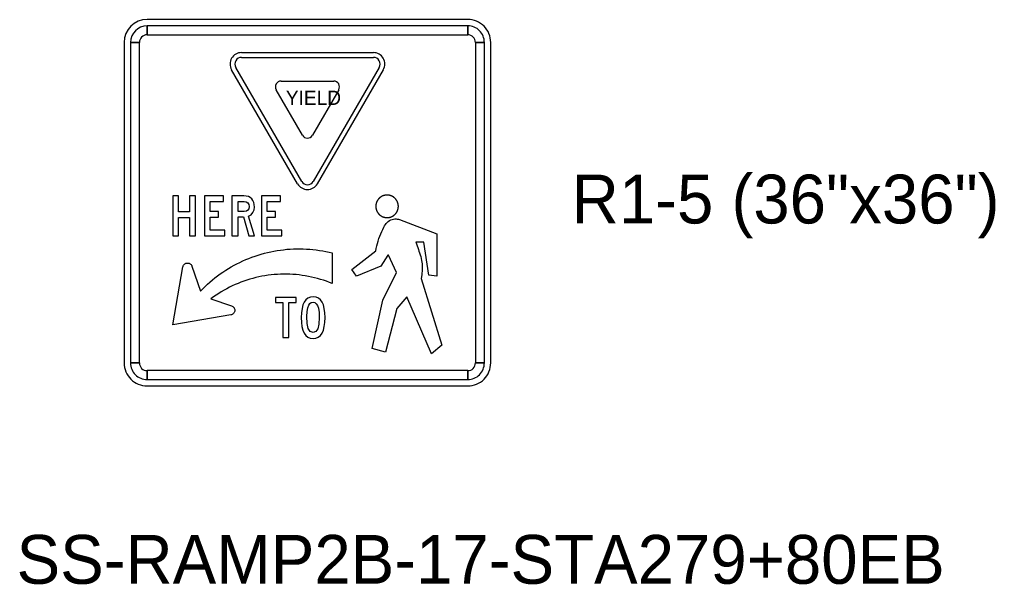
# Model space of a CAD drawing. Extents: x 620856.8 to 620948.6, y 415598.8 to 415658.2.
# Drawn here: x 620886.92 to 620894.91, y 415617.41 to 415622.04 of the extents above; entities that cross this region are included whole.
import ezdxf

# ---------------------------------------------------------------- set-up
doc = ezdxf.new("R2010")
doc.units = 0
doc.layers.add('SIGNS', color=7, linetype='Continuous')

msp = doc.modelspace()

# ---------------------------------------------------------------- linework, layer by layer
at = {"layer": 'SIGNS'}
for p, q in [((620890.5903, 415622.0407), (620887.9653, 415622.0407)), ((620890.5903, 415622.0407), (620887.9653, 415622.0407)), ((620887.9653, 415621.9157), (620887.9653, 415621.9886)), ((620890.5903, 415621.9886), (620890.5903, 415621.9157)), ((620887.7778, 415621.8532), (620887.7778, 415619.2282)), ((620887.7778, 415621.8532), (620887.7778, 415619.2282)), ((620887.8298, 415621.8532), (620887.9028, 415621.8532)), ((620890.6528, 415621.8532), (620890.7257, 415621.8532)), ((620890.7778, 415619.2282), (620890.7778, 415621.8532)), ((620890.7778, 415619.2282), (620890.7778, 415621.8532)), ((620888.7384, 415621.7698), (620889.8171, 415621.7698)), ((620888.7384, 415621.7309), (620889.8171, 415621.7309)), ((620889.1968, 415620.6954), (620888.6575, 415621.6296)), ((620889.2305, 415620.7149), (620888.6912, 415621.649)), ((620889.8643, 415621.649), (620889.325, 415620.7149)), ((620889.8981, 415621.6296), (620889.3587, 415620.6954)), ((620889.0623, 415621.5361), (620889.4932, 415621.5361)), ((620889.2373, 415621.0928), (620889.0219, 415621.4659)), ((620889.5337, 415621.4659), (620889.3182, 415621.0928)), ((620889.931, 415620.3798), (620889.9397, 415620.3879)), ((620889.9397, 415620.3879), (620889.9493, 415620.3946)), ((620889.9493, 415620.3946), (620889.9592, 415620.4002)), ((620889.9592, 415620.4002), (620889.9699, 415620.4044)), ((620889.9699, 415620.4044), (620889.9811, 415620.4069)), ((620889.9811, 415620.4069), (620889.9928, 415620.4079)), ((620889.9928, 415620.4079), (620890.0032, 415620.4078)), ((620890.0032, 415620.4078), (620890.0132, 415620.4069)), ((620890.0132, 415620.4069), (620890.0229, 415620.405)), ((620890.0229, 415620.405), (620890.0323, 415620.4021)), ((620890.0323, 415620.4021), (620890.3379, 415620.2852)), ((620889.8855, 415620.3038), (620889.8939, 415620.3225)), ((620889.8939, 415620.3225), (620889.9026, 415620.3411)), ((620889.9026, 415620.3411), (620889.9086, 415620.3514)), ((620889.9086, 415620.3514), (620889.9154, 415620.3615)), ((620889.9154, 415620.3615), (620889.9229, 415620.3709)), ((620889.9229, 415620.3709), (620889.931, 415620.3798)), ((620889.8508, 415620.2071), (620889.8566, 415620.227)), ((620889.8566, 415620.227), (620889.8631, 415620.2465)), ((620889.8631, 415620.2465), (620889.8701, 415620.2659)), ((620889.8701, 415620.2659), (620889.8776, 415620.2849)), ((620889.8776, 415620.2849), (620889.8855, 415620.3038)), ((620890.3379, 415620.2852), (620890.3379, 415619.9401)), ((620889.6403, 415619.9951), (620889.8381, 415620.1458)), ((620889.8381, 415620.1458), (620889.8415, 415620.1665)), ((620889.8415, 415620.1665), (620889.8458, 415620.187)), ((620889.8458, 415620.187), (620889.8508, 415620.2071)), ((620890.229, 415620.2187), (620890.1657, 415620.2182)), ((620890.1657, 415620.2182), (620890.1705, 415620.2033)), ((620890.1705, 415620.2033), (620890.1754, 415620.1885)), ((620890.1754, 415620.1885), (620890.1804, 415620.1737)), ((620890.1804, 415620.1737), (620890.1855, 415620.1588)), ((620890.1855, 415620.1588), (620890.1904, 415620.144)), ((620890.2714, 415619.9479), (620890.229, 415620.2187)), ((620889.4548, 415620.1357), (620889.4811, 415620.1296)), ((620889.4811, 415620.1296), (620889.4811, 415619.8785)), ((620889.9366, 415620.1118), (620889.8796, 415620.0214)), ((620889.9374, 415620.1119), (620889.9366, 415620.1118)), ((620889.9382, 415620.1119), (620889.9374, 415620.1119)), ((620889.9387, 415620.1118), (620889.9382, 415620.1119)), ((620889.9395, 415620.1116), (620889.9387, 415620.1118)), ((620889.94, 415620.1113), (620889.9395, 415620.1116)), ((620890.0057, 415619.9704), (620889.94, 415620.1113)), ((620890.1904, 415620.144), (620890.1953, 415620.1293)), ((620890.1953, 415620.1293), (620890.2, 415620.1143)), ((620890.2, 415620.1143), (620890.2045, 415620.0993)), ((620890.2045, 415620.0993), (620890.2085, 415620.084)), ((620890.2085, 415620.084), (620890.2124, 415620.0687)), ((620890.2124, 415620.0687), (620890.2146, 415620.0541)), ((620888.1769, 415619.5407), (620888.2583, 415620.0147)), ((620888.3329, 415620.0208), (620888.4029, 415619.8176)), ((620889.6802, 415619.9401), (620889.6403, 415619.9951)), ((620889.8796, 415620.0214), (620889.6802, 415619.9401)), ((620890.2146, 415620.0541), (620890.2162, 415620.0392)), ((620890.2169, 415619.9944), (620890.216, 415619.9794)), ((620890.2162, 415620.0392), (620890.217, 415620.0242)), ((620890.2173, 415620.0094), (620890.2169, 415619.9944)), ((620890.217, 415620.0242), (620890.2173, 415620.0094)), ((620889.8948, 415619.742), (620890.0063, 415619.9698)), ((620890.0063, 415619.9698), (620890.0057, 415619.9704)), ((620890.213, 415619.9494), (620890.2085, 415619.9199)), ((620890.2085, 415619.9199), (620890.3786, 415619.3738)), ((620890.2147, 415619.9644), (620890.213, 415619.9494)), ((620890.216, 415619.9794), (620890.2147, 415619.9644)), ((620890.3379, 415619.9401), (620890.2714, 415619.9479)), ((620889.4811, 415619.8785), (620889.4571, 415619.888)), ((620888.4881, 415619.7545), (620888.657, 415619.6966)), ((620890.0909, 415619.7696), (620890.0101, 415619.6756)), ((620890.2936, 415619.3023), (620890.0909, 415619.7696)), ((620889.8074, 415619.3468), (620889.8948, 415619.742)), ((620890.0101, 415619.6756), (620889.916, 415619.3178)), ((620888.651, 415619.6221), (620888.1769, 415619.5407)), ((620889.916, 415619.3178), (620889.8074, 415619.3468)), ((620890.3786, 415619.3738), (620890.2936, 415619.3023)), ((620887.9028, 415619.2282), (620887.8298, 415619.2282)), ((620890.7257, 415619.2282), (620890.6528, 415619.2282)), ((620887.9653, 415619.0927), (620887.9653, 415619.1657)), ((620890.5903, 415619.1657), (620890.5903, 415619.0927)), ((620887.9653, 415619.0407), (620890.5903, 415619.0407)), ((620887.9653, 415619.0407), (620890.5903, 415619.0407))]:
    msp.add_line(p, q, dxfattribs=at)
for points in [[(620890.5903, 415621.9886), (620887.9653, 415621.9886), (620887.9653, 415621.9157), (620890.5903, 415621.9157), (620890.5903, 415621.9886), (620890.5903, 415621.9886)], [(620887.8298, 415621.8532), (620887.8298, 415619.2282), (620887.9028, 415619.2282), (620887.9028, 415621.8532), (620887.8298, 415621.8532), (620887.8298, 415621.8532)], [(620890.7257, 415619.2282), (620890.7257, 415621.8532), (620890.6528, 415621.8532), (620890.6528, 415619.2282), (620890.7257, 415619.2282), (620890.7257, 415619.2282)], [(620888.1769, 415620.2698), (620888.2218, 415620.2698), (620888.2218, 415620.4199), (620888.3115, 415620.4199), (620888.3115, 415620.2698), (620888.3615, 415620.2698), (620888.3615, 415620.5967), (620888.3115, 415620.5967), (620888.3115, 415620.4656), (620888.2218, 415620.4656), (620888.2218, 415620.5967), (620888.1769, 415620.5967)], [(620888.6027, 415620.3147), (620888.4823, 415620.3147), (620888.4823, 415620.4236), (620888.5506, 415620.4236), (620888.5506, 415620.4685), (620888.4823, 415620.4685), (620888.4823, 415620.5518), (620888.5902, 415620.5518), (620888.5902, 415620.5967), (620888.4346, 415620.5967), (620888.4346, 415620.2698), (620888.6027, 415620.2698)], [(620889.0691, 415620.3147), (620888.9487, 415620.3147), (620888.9487, 415620.4236), (620889.017, 415620.4236), (620889.017, 415620.4685), (620888.9487, 415620.4685), (620888.9487, 415620.5518), (620889.0566, 415620.5518), (620889.0566, 415620.5967), (620888.9009, 415620.5967), (620888.9009, 415620.2698), (620889.0691, 415620.2698)], [(620889.077, 415619.4365), (620889.1245, 415619.4365), (620889.1245, 415619.7223), (620889.1855, 415619.7223), (620889.1855, 415619.7634), (620889.0173, 415619.7634), (620889.0173, 415619.7223), (620889.077, 415619.7223)], [(620887.9653, 415619.0927), (620890.5903, 415619.0927), (620890.5903, 415619.1657), (620887.9653, 415619.1657), (620887.9653, 415619.0927), (620887.9653, 415619.0927)]]:
    msp.add_lwpolyline(points, close=True, dxfattribs=at)
for points in [[(620888.6594, 415620.2698), (620888.7107, 415620.2698), (620888.7107, 415620.4255), (620888.7543, 415620.4255), (620888.7971, 415620.2698), (620888.844, 415620.2698), (620888.7965, 415620.431), (620888.8168, 415620.4424), (620888.8322, 415620.4604), (620888.841, 415620.4813), (620888.844, 415620.5052), (620888.8426, 415620.5248), (620888.8384, 415620.5424), (620888.8315, 415620.5579), (620888.8219, 415620.5712), (620888.8092, 415620.5823), (620888.7941, 415620.5903), (620888.7768, 415620.5951), (620888.7572, 415620.5967), (620888.6594, 415620.5967), (620888.6594, 415620.2698)], [(620888.7107, 415620.4685), (620888.7107, 415620.5518), (620888.7587, 415620.5518), (620888.7755, 415620.549), (620888.7889, 415620.5405), (620888.7975, 415620.5272), (620888.8004, 415620.51), (620888.7978, 415620.4917), (620888.7903, 415620.4789), (620888.7778, 415620.471), (620888.7602, 415620.4685), (620888.7107, 415620.4685)], [(620889.913, 415620.6017), (620889.9114, 415620.6014), (620889.9098, 415620.601), (620889.9082, 415620.6007), (620889.9066, 415620.6003), (620889.9051, 415620.5999), (620889.9035, 415620.5995), (620889.902, 415620.599), (620889.9004, 415620.5985), (620889.8989, 415620.598), (620889.8974, 415620.5974), (620889.8959, 415620.5969), (620889.8944, 415620.5963), (620889.8929, 415620.5956), (620889.8914, 415620.595), (620889.8899, 415620.5943), (620889.8885, 415620.5936), (620889.8871, 415620.5929), (620889.8856, 415620.5921), (620889.8842, 415620.5913), (620889.8828, 415620.5905), (620889.8814, 415620.5897), (620889.88, 415620.5888), (620889.8787, 415620.588), (620889.8774, 415620.5871), (620889.876, 415620.5861), (620889.8747, 415620.5852), (620889.8734, 415620.5842), (620889.8721, 415620.5832), (620889.8709, 415620.5822), (620889.8697, 415620.5812), (620889.8684, 415620.5801), (620889.8672, 415620.5791), (620889.866, 415620.578), (620889.8649, 415620.5768), (620889.8637, 415620.5757), (620889.8626, 415620.5745), (620889.8615, 415620.5734), (620889.8604, 415620.5722), (620889.8594, 415620.5709), (620889.8583, 415620.5697), (620889.8573, 415620.5685), (620889.8563, 415620.5672), (620889.8553, 415620.5659), (620889.8544, 415620.5646), (620889.8534, 415620.5633), (620889.8525, 415620.5619), (620889.8517, 415620.5606), (620889.8508, 415620.5592), (620889.85, 415620.5578), (620889.8492, 415620.5564), (620889.8484, 415620.555), (620889.8476, 415620.5536), (620889.8469, 415620.5522), (620889.8462, 415620.5507), (620889.8455, 415620.5492), (620889.8448, 415620.5478), (620889.8442, 415620.5463), (620889.8436, 415620.5448), (620889.843, 415620.5433), (620889.8425, 415620.5418), (620889.8419, 415620.5402), (620889.8414, 415620.5387), (620889.841, 415620.5372), (620889.8405, 415620.5356), (620889.8401, 415620.534), (620889.8397, 415620.5325), (620889.8393, 415620.5309), (620889.839, 415620.5293), (620889.8387, 415620.5277), (620889.8384, 415620.5261), (620889.8381, 415620.5246), (620889.8379, 415620.523), (620889.8377, 415620.5213), (620889.8376, 415620.5197), (620889.8374, 415620.5181), (620889.8373, 415620.5165), (620889.8372, 415620.5149), (620889.8372, 415620.5133), (620889.8371, 415620.5117), (620889.8371, 415620.5101), (620889.8372, 415620.5084), (620889.8372, 415620.5068), (620889.8373, 415620.5052), (620889.8374, 415620.5036), (620889.8376, 415620.502), (620889.8377, 415620.5004), (620889.8379, 415620.4988), (620889.8381, 415620.4972), (620889.8384, 415620.4956), (620889.8387, 415620.494), (620889.839, 415620.4924), (620889.8393, 415620.4908), (620889.8397, 415620.4893), (620889.8401, 415620.4877), (620889.8405, 415620.4861), (620889.841, 415620.4846), (620889.8414, 415620.483), (620889.8419, 415620.4815), (620889.8425, 415620.48), (620889.843, 415620.4785)], [(620890.0217, 415620.5109), (620890.0217, 415620.5125), (620890.0217, 415620.5141), (620890.0216, 415620.5157), (620890.0215, 415620.5173), (620890.0214, 415620.5189), (620890.0212, 415620.5205), (620890.021, 415620.5221), (620890.0208, 415620.5238), (620890.0206, 415620.5253), (620890.0203, 415620.5269), (620890.02, 415620.5285), (620890.0197, 415620.5301), (620890.0193, 415620.5317), (620890.019, 415620.5333), (620890.0185, 415620.5348), (620890.0181, 415620.5364), (620890.0177, 415620.5379), (620890.0172, 415620.5395), (620890.0167, 415620.541), (620890.0161, 415620.5425), (620890.0155, 415620.544), (620890.015, 415620.5455), (620890.0143, 415620.547), (620890.0137, 415620.5485), (620890.013, 415620.55), (620890.0123, 415620.5514), (620890.0116, 415620.5529), (620890.0108, 415620.5543), (620890.0101, 415620.5557), (620890.0093, 415620.5571), (620890.0085, 415620.5585), (620890.0076, 415620.5599), (620890.0067, 415620.5613), (620890.0058, 415620.5626), (620890.0049, 415620.5639), (620890.004, 415620.5652), (620890.003, 415620.5665), (620890.002, 415620.5678), (620890.001, 415620.5691), (620890, 415620.5703), (620889.999, 415620.5716), (620889.9979, 415620.5728), (620889.9968, 415620.574), (620889.9957, 415620.5751), (620889.9945, 415620.5763), (620889.9934, 415620.5774), (620889.9922, 415620.5785), (620889.991, 415620.5796), (620889.9898, 415620.5807), (620889.9886, 415620.5817), (620889.9873, 415620.5827), (620889.9861, 415620.5837), (620889.9848, 415620.5847), (620889.9835, 415620.5857), (620889.9822, 415620.5866), (620889.9808, 415620.5875), (620889.9795, 415620.5884), (620889.9781, 415620.5893), (620889.9767, 415620.5901), (620889.9753, 415620.5909), (620889.9739, 415620.5917), (620889.9725, 415620.5925), (620889.9711, 415620.5932), (620889.9696, 415620.5939), (620889.9682, 415620.5946), (620889.9667, 415620.5953), (620889.9652, 415620.5959), (620889.9637, 415620.5966), (620889.9622, 415620.5971), (620889.9607, 415620.5977), (620889.9592, 415620.5982), (620889.9576, 415620.5987), (620889.9561, 415620.5992), (620889.9545, 415620.5997), (620889.953, 415620.6001), (620889.9514, 415620.6005), (620889.9498, 415620.6009), (620889.9483, 415620.6012), (620889.9467, 415620.6015), (620889.9451, 415620.6018), (620889.9435, 415620.6021), (620889.9419, 415620.6023), (620889.9403, 415620.6025), (620889.9387, 415620.6027), (620889.9371, 415620.6028), (620889.9355, 415620.603), (620889.9339, 415620.6031), (620889.9322, 415620.6031), (620889.9306, 415620.6032), (620889.929, 415620.6032), (620889.9274, 415620.6031), (620889.9258, 415620.6031), (620889.9242, 415620.603), (620889.9226, 415620.6029), (620889.921, 415620.6028), (620889.9193, 415620.6026), (620889.9177, 415620.6024), (620889.9161, 415620.6022), (620889.9145, 415620.602), (620889.913, 415620.6017)], [(620889.843, 415620.4785), (620889.8436, 415620.477), (620889.8442, 415620.4755), (620889.8448, 415620.474), (620889.8455, 415620.4725), (620889.8462, 415620.471), (620889.8469, 415620.4696), (620889.8476, 415620.4681), (620889.8484, 415620.4667), (620889.8492, 415620.4653), (620889.85, 415620.4639), (620889.8508, 415620.4625), (620889.8517, 415620.4612), (620889.8525, 415620.4598), (620889.8534, 415620.4585), (620889.8544, 415620.4571), (620889.8553, 415620.4558), (620889.8563, 415620.4546), (620889.8573, 415620.4533), (620889.8583, 415620.452), (620889.8594, 415620.4508), (620889.8604, 415620.4496), (620889.8615, 415620.4484), (620889.8626, 415620.4472), (620889.8637, 415620.446), (620889.8649, 415620.4449), (620889.866, 415620.4438), (620889.8672, 415620.4427), (620889.8684, 415620.4416), (620889.8697, 415620.4405), (620889.8709, 415620.4395), (620889.8721, 415620.4385), (620889.8734, 415620.4375), (620889.8747, 415620.4365), (620889.876, 415620.4356), (620889.8774, 415620.4347), (620889.8787, 415620.4338), (620889.88, 415620.4329), (620889.8814, 415620.432), (620889.8828, 415620.4312), (620889.8842, 415620.4304), (620889.8856, 415620.4296), (620889.8871, 415620.4289), (620889.8885, 415620.4281), (620889.8899, 415620.4274), (620889.8914, 415620.4268), (620889.8929, 415620.4261), (620889.8944, 415620.4255), (620889.8959, 415620.4249), (620889.8974, 415620.4243), (620889.8989, 415620.4238), (620889.9004, 415620.4232), (620889.902, 415620.4228), (620889.9035, 415620.4223), (620889.9051, 415620.4218), (620889.9066, 415620.4214), (620889.9082, 415620.421), (620889.9098, 415620.4207), (620889.9114, 415620.4204), (620889.913, 415620.4201), (620889.9145, 415620.4198), (620889.9161, 415620.4195), (620889.9177, 415620.4193), (620889.9193, 415620.4191), (620889.921, 415620.419), (620889.9226, 415620.4188), (620889.9242, 415620.4187), (620889.9258, 415620.4187), (620889.9274, 415620.4186), (620889.929, 415620.4186), (620889.9306, 415620.4186), (620889.9322, 415620.4186), (620889.9339, 415620.4187), (620889.9355, 415620.4188), (620889.9371, 415620.4189), (620889.9387, 415620.419), (620889.9403, 415620.4192), (620889.9419, 415620.4194), (620889.9435, 415620.4197), (620889.9451, 415620.4199), (620889.9467, 415620.4202), (620889.9483, 415620.4205), (620889.9498, 415620.4209), (620889.9514, 415620.4212), (620889.953, 415620.4216), (620889.9545, 415620.4221), (620889.9561, 415620.4225), (620889.9576, 415620.423), (620889.9592, 415620.4235), (620889.9607, 415620.424), (620889.9622, 415620.4246), (620889.9637, 415620.4252), (620889.9652, 415620.4258), (620889.9667, 415620.4264), (620889.9682, 415620.4271), (620889.9696, 415620.4278), (620889.9711, 415620.4285), (620889.9725, 415620.4293), (620889.9739, 415620.43), (620889.9753, 415620.4308), (620889.9767, 415620.4316)], [(620889.9767, 415620.4316), (620889.9781, 415620.4325), (620889.9795, 415620.4333), (620889.9808, 415620.4342), (620889.9822, 415620.4351), (620889.9835, 415620.4361), (620889.9848, 415620.437), (620889.9861, 415620.438), (620889.9873, 415620.439), (620889.9886, 415620.44), (620889.9898, 415620.4411), (620889.991, 415620.4421), (620889.9922, 415620.4432), (620889.9934, 415620.4443), (620889.9945, 415620.4455), (620889.9957, 415620.4466), (620889.9968, 415620.4478), (620889.9979, 415620.449), (620889.999, 415620.4502), (620890, 415620.4514), (620890.001, 415620.4527), (620890.002, 415620.4539), (620890.003, 415620.4552), (620890.004, 415620.4565), (620890.0049, 415620.4578), (620890.0058, 415620.4591), (620890.0067, 415620.4605), (620890.0076, 415620.4618), (620890.0085, 415620.4632), (620890.0093, 415620.4646), (620890.0101, 415620.466), (620890.0108, 415620.4674), (620890.0116, 415620.4689), (620890.0123, 415620.4703), (620890.013, 415620.4718), (620890.0137, 415620.4732), (620890.0143, 415620.4747), (620890.015, 415620.4762), (620890.0155, 415620.4777), (620890.0161, 415620.4792), (620890.0167, 415620.4807), (620890.0172, 415620.4823), (620890.0177, 415620.4838), (620890.0181, 415620.4854), (620890.0185, 415620.4869), (620890.019, 415620.4885), (620890.0193, 415620.4901), (620890.0197, 415620.4916), (620890.02, 415620.4932), (620890.0203, 415620.4948), (620890.0206, 415620.4964), (620890.0208, 415620.498), (620890.021, 415620.4996), (620890.0212, 415620.5012), (620890.0214, 415620.5028), (620890.0215, 415620.5044), (620890.0216, 415620.506), (620890.0217, 415620.5076), (620890.0217, 415620.5093), (620890.0217, 415620.5109), (620890.0217, 415620.5109), (620890.0217, 415620.5109)], [(620888.4029, 415619.8176), (620888.4216, 415619.8367), (620888.4406, 415619.8553), (620888.46, 415619.8736), (620888.4801, 415619.8914), (620888.5007, 415619.9086), (620888.5212, 415619.9253), (620888.5425, 415619.9417), (620888.5642, 415619.9573), (620888.5863, 415619.9725), (620888.6087, 415619.9873), (620888.6312, 415620.0014), (620888.6544, 415620.0151), (620888.6776, 415620.028), (620888.7012, 415620.0406), (620888.7251, 415620.0524), (620888.7495, 415620.0638), (620888.7738, 415620.0744), (620888.7986, 415620.0847), (620888.8237, 415620.0942), (620888.8488, 415620.1033), (620888.8743, 415620.1117), (620888.8998, 415620.1193), (620888.9256, 415620.1266), (620888.9515, 415620.133), (620888.9774, 415620.1387), (620889.0036, 415620.1441), (620889.0299, 415620.1486), (620889.0565, 415620.1528), (620889.0831, 415620.1559), (620889.1098, 415620.1589), (620889.1364, 415620.1608), (620889.163, 415620.1623), (620889.1897, 415620.1631), (620889.2163, 415620.1631), (620889.2433, 415620.1627), (620889.2699, 415620.1616), (620889.2966, 415620.1597), (620889.3232, 415620.1574), (620889.3498, 415620.1543), (620889.3761, 415620.1505), (620889.4027, 415620.1463), (620889.429, 415620.1414), (620889.4548, 415620.1357)], [(620888.2583, 415620.0147), (620888.2595, 415620.0196), (620888.2614, 415620.0242), (620888.2641, 415620.0288), (620888.2667, 415620.033), (620888.2705, 415620.0368), (620888.2743, 415620.0398), (620888.2789, 415620.0425), (620888.2835, 415620.0444), (620888.2884, 415620.0459), (620888.2933, 415620.0467), (620888.2983, 415620.0467), (620888.3036, 415620.0463), (620888.3086, 415620.0448), (620888.3131, 415620.0429), (620888.3177, 415620.0406), (620888.3215, 415620.0375), (620888.3253, 415620.0337), (620888.3283, 415620.0299), (620888.331, 415620.0254), (620888.3329, 415620.0208)], [(620889.4571, 415619.888), (620889.4332, 415619.8971), (620889.4092, 415619.9051), (620889.3848, 415619.9127), (620889.3601, 415619.92), (620889.3358, 415619.9264), (620889.3106, 415619.9321), (620889.2855, 415619.9375), (620889.2604, 415619.9417), (620889.2353, 415619.9458), (620889.2102, 415619.9489), (620889.1847, 415619.9515), (620889.1592, 415619.9535), (620889.1337, 415619.955), (620889.1083, 415619.9557), (620889.0828, 415619.9557), (620889.0573, 415619.955), (620889.0318, 415619.9538), (620889.0063, 415619.9519), (620888.9808, 415619.9493), (620888.9553, 415619.9462), (620888.9302, 415619.9424), (620888.9051, 415619.9379), (620888.88, 415619.9329), (620888.8553, 415619.9272), (620888.8305, 415619.9207), (620888.8058, 415619.9139), (620888.7814, 415619.9063), (620888.7575, 415619.8983), (620888.7335, 415619.8895), (620888.7095, 415619.88), (620888.6863, 415619.8701), (620888.6628, 415619.8595), (620888.6399, 415619.8484), (620888.6171, 415619.8367), (620888.595, 415619.8245), (620888.573, 415619.8115), (620888.5513, 415619.7982), (620888.5296, 415619.7842), (620888.5087, 415619.7697), (620888.4881, 415619.7545)], [(620889.4218, 415619.6004), (620889.4202, 415619.64), (620889.4157, 415619.6745), (620889.4082, 415619.7035), (620889.3977, 415619.7274), (620889.384, 415619.7459), (620889.3674, 415619.7592), (620889.3478, 415619.7671), (620889.3253, 415619.7698), (620889.3023, 415619.7671), (620889.2823, 415619.7592), (620889.2655, 415619.7459), (620889.2518, 415619.7274), (620889.2411, 415619.7035), (620889.2334, 415619.6745), (620889.2288, 415619.64), (620889.2273, 415619.6004), (620889.2287, 415619.5604), (620889.2332, 415619.5258), (620889.2407, 415619.4965), (620889.2513, 415619.4726), (620889.2647, 415619.4539), (620889.2812, 415619.4407), (620889.3007, 415619.4327), (620889.3233, 415619.4301), (620889.3463, 415619.4327), (620889.3663, 415619.4407), (620889.3833, 415619.4539), (620889.3972, 415619.4726), (620889.4079, 415619.4965), (620889.4156, 415619.5258), (620889.4202, 415619.5604), (620889.4218, 415619.6004)], [(620888.657, 415619.6966), (620888.6616, 415619.6944), (620888.6662, 415619.6921), (620888.67, 415619.6887), (620888.6738, 415619.6852), (620888.6768, 415619.681), (620888.6791, 415619.6769), (620888.681, 415619.6719), (620888.6825, 415619.667), (620888.6829, 415619.662), (620888.6829, 415619.6567), (620888.6822, 415619.6518), (620888.6806, 415619.6468), (620888.6787, 415619.6422), (620888.6761, 415619.6381), (620888.673, 415619.6339), (620888.6692, 415619.6304), (620888.665, 415619.6274), (620888.6605, 415619.6251), (620888.6559, 415619.6232), (620888.651, 415619.6221)], [(620889.3748, 415619.6019), (620889.3715, 415619.5475), (620889.3619, 415619.5087), (620889.346, 415619.4854), (620889.3238, 415619.4776), (620889.3012, 415619.4859), (620889.285, 415619.5107), (620889.2754, 415619.5521), (620889.2722, 415619.6102), (620889.2742, 415619.6487), (620889.2804, 415619.6808), (620889.2878, 415619.7004), (620889.2975, 415619.7146), (620889.3095, 415619.723), (620889.3238, 415619.7259), (620889.3378, 415619.7228), (620889.3497, 415619.7135), (620889.3594, 415619.698), (620889.3669, 415619.6764), (620889.3728, 415619.6425), (620889.3748, 415619.6019)]]:
    msp.add_lwpolyline(points, dxfattribs=at)
for centre, radius, start, end in [((620887.9653, 415621.8532), 0.1875, 90.00021, 179.99985), ((620887.9653, 415621.8532), 0.1875, 90.00021, 179.99985), ((620887.9653, 415621.8532), 0.1354, 90.00021, 179.99985), ((620890.5903, 415621.8532), 0.1875, 0, 90.00021), ((620890.5903, 415621.8532), 0.1875, 0, 90.00021), ((620890.5903, 415621.8532), 0.1354, 0, 90.00021), ((620887.9653, 415621.8532), 0.0625, 90.00021, 179.99985), ((620890.5903, 415621.8532), 0.0625, 0, 90.00021), ((620888.7384, 415621.6763), 0.0935, 90, 210), ((620889.8171, 415621.6763), 0.0935, 330.00001, 90), ((620888.7384, 415621.6763), 0.0545, 90, 210), ((620889.8171, 415621.6763), 0.0545, 330.00001, 90), ((620889.0623, 415621.4893), 0.0468, 90, 210), ((620889.4932, 415621.4893), 0.0468, 330.00001, 90), ((620889.2778, 415621.1162), 0.0468, 210, 330.00001), ((620889.2778, 415620.7422), 0.0545, 210, 330.00001), ((620889.2778, 415620.7422), 0.0935, 210, 330.00001), ((620887.9653, 415619.2282), 0.1875, 179.99985, 270.00006), ((620887.9653, 415619.2282), 0.1875, 179.99985, 270.00006), ((620887.9653, 415619.2282), 0.1354, 179.99985, 270.00006), ((620887.9653, 415619.2282), 0.0625, 179.99985, 270.00006), ((620890.5903, 415619.2282), 0.1875, 270.00006, 0.00027), ((620890.5903, 415619.2282), 0.1875, 270.00006, 0.00027), ((620890.5903, 415619.2282), 0.1354, 270.00006, 0.00027), ((620890.5903, 415619.2282), 0.0625, 270.00006, 0.00027)]:
    msp.add_arc(centre, radius, start, end, dxfattribs=at)

# ---------------------------------------------------------------- texts
for s, height, rotation, p in [('YIELD', 0.11688, 360, (620889.1009, 415621.3413)), ('R1-5 (36"x36")', 0.4, 0, (620891.4402, 415620.3705)), ('SS-RAMP2B-17-STA279+80EB', 0.4, 0, (620886.8972, 415617.4203))]:
    msp.add_text(s, height=height, rotation=rotation, dxfattribs=at).set_placement(p)

doc.saveas('drawing.dxf')
